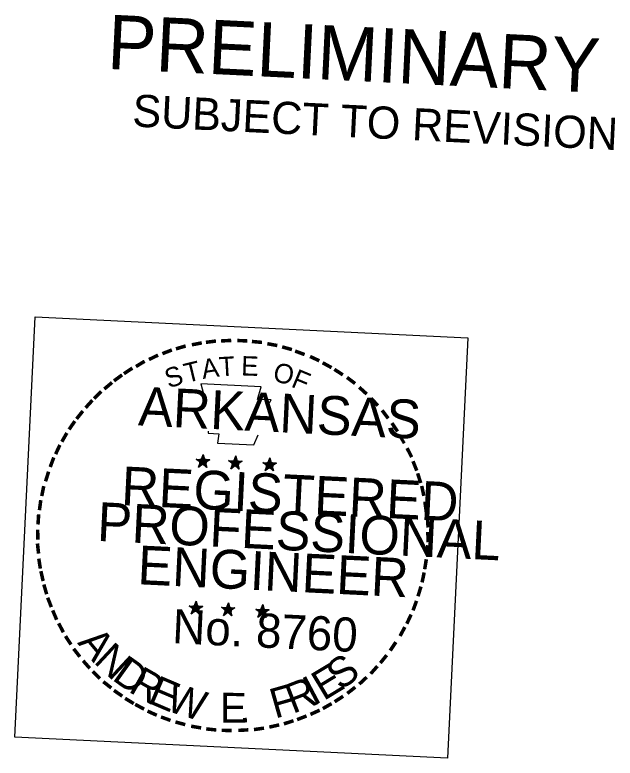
# Model space of a CAD drawing. Extents: x 669100 to 670801, y 741155 to 743955.
# Drawn here: x 669099.6 to 669177, y 743722.6 to 743818.4 of the extents above; entities that cross this region are included whole.
import ezdxf

# ---------------------------------------------------------------- set-up
doc = ezdxf.new("R2010")
doc.units = 0
doc.layers.add('R_Border PE', color=7, linetype='Continuous')
doc.layers.add('R_Border Prem', color=7, linetype='Continuous')

msp = doc.modelspace()

# ---------------------------------------------------------------- linework, layer by layer
at = {"layer": 'R_Border PE'}
for p, q in [((669123.901, 743761.791), (669123.745, 743761.172)), ((669123.901, 743761.791), (669123.769, 743761.146)), ((669123.901, 743761.791), (669123.845, 743761.168)), ((669123.856, 743760.867), (669123.901, 743761.791)), ((669123.901, 743761.791), (669124.044, 743761.133)), ((669123.901, 743761.791), (669123.995, 743761.16)), ((669123.901, 743761.791), (669123.945, 743761.163)), ((669122.995, 743761.184), (669123.856, 743760.867)), ((669122.995, 743761.184), (669123.642, 743761.102)), ((669122.995, 743761.184), (669123.639, 743761.052)), ((669122.995, 743761.184), (669123.612, 743761.004)), ((669122.995, 743761.184), (669123.607, 743760.904)), ((669122.995, 743761.184), (669123.58, 743760.855)), ((669122.995, 743761.184), (669123.577, 743760.805)), ((669123.295, 743760.143), (669123.856, 743760.867)), ((669124.743, 743761.099), (669123.856, 743760.867)), ((669124.369, 743760.091), (669123.856, 743760.867)), ((669124.743, 743761.099), (669123.966, 743761.087)), ((669124.743, 743761.099), (669124.01, 743760.959)), ((669124.743, 743761.099), (669124.013, 743761.009)), ((669124.369, 743760.091), (669124.054, 743760.832)), ((669124.369, 743760.091), (669124.105, 743760.855)), ((669124.743, 743761.099), (669124.183, 743760.901)), ((669124.743, 743761.099), (669124.231, 743760.873)), ((669124.743, 743761.099), (669124.255, 743760.847)), ((669127.165, 743760.981), (669128.026, 743760.664)), ((669127.165, 743760.981), (669127.812, 743760.9)), ((669127.165, 743760.981), (669127.81, 743760.85)), ((669127.165, 743760.981), (669127.782, 743760.801)), ((669127.165, 743760.981), (669127.752, 743760.702)), ((669127.165, 743760.981), (669127.75, 743760.653)), ((669127.165, 743760.981), (669127.747, 743760.603)), ((669128.071, 743761.588), (669127.915, 743760.97)), ((669128.071, 743761.588), (669127.939, 743760.944)), ((669128.071, 743761.588), (669127.99, 743760.966)), ((669128.026, 743760.664), (669128.071, 743761.588)), ((669128.913, 743760.896), (669128.026, 743760.664)), ((669128.071, 743761.588), (669128.214, 743760.93)), ((669128.071, 743761.588), (669128.165, 743760.958)), ((669128.071, 743761.588), (669128.09, 743760.961)), ((669128.913, 743760.896), (669128.137, 743760.884)), ((669128.913, 743760.896), (669128.18, 743760.757)), ((669128.913, 743760.896), (669128.183, 743760.807)), ((669128.913, 743760.896), (669128.353, 743760.698)), ((669128.913, 743760.896), (669128.402, 743760.671)), ((669128.913, 743760.896), (669128.425, 743760.645)), ((669132.488, 743761.324), (669132.309, 743760.731)), ((669132.488, 743761.324), (669132.358, 743760.704)), ((669132.488, 743761.324), (669132.408, 743760.702)), ((669132.444, 743760.425), (669132.488, 743761.324)), ((669132.488, 743761.324), (669132.633, 743760.691)), ((669132.488, 743761.324), (669132.583, 743760.693)), ((669132.488, 743761.324), (669132.509, 743760.722)), ((669123.295, 743760.143), (669123.604, 743760.829)), ((669123.295, 743760.143), (669123.625, 743760.753)), ((669123.295, 743760.143), (669123.674, 743760.725)), ((669123.295, 743760.143), (669123.846, 743760.667)), ((669123.295, 743760.143), (669123.745, 743760.647)), ((669123.295, 743760.143), (669123.867, 743760.591)), ((669124.369, 743760.091), (669123.842, 743760.592)), ((669124.369, 743760.091), (669123.846, 743760.667)), ((669124.369, 743760.091), (669123.945, 743760.637)), ((669124.369, 743760.091), (669124.024, 743760.733)), ((669127.465, 743759.941), (669128.026, 743760.664)), ((669127.465, 743759.941), (669127.774, 743760.626)), ((669127.465, 743759.941), (669127.795, 743760.55)), ((669127.465, 743759.941), (669127.844, 743760.523)), ((669127.465, 743759.941), (669128.016, 743760.464)), ((669127.465, 743759.941), (669127.915, 743760.444)), ((669127.465, 743759.941), (669128.037, 743760.388)), ((669128.539, 743759.888), (669128.012, 743760.389)), ((669128.539, 743759.888), (669128.016, 743760.464)), ((669128.539, 743759.888), (669128.026, 743760.664)), ((669128.539, 743759.888), (669128.115, 743760.435)), ((669128.539, 743759.888), (669128.195, 743760.531)), ((669128.539, 743759.888), (669128.224, 743760.629)), ((669128.539, 743759.888), (669128.275, 743760.652)), ((669131.584, 743760.742), (669132.444, 743760.425)), ((669131.584, 743760.742), (669132.229, 743760.635)), ((669131.584, 743760.742), (669132.202, 743760.587)), ((669131.584, 743760.742), (669132.201, 743760.562)), ((669131.584, 743760.742), (669132.171, 743760.463)), ((669131.584, 743760.742), (669132.168, 743760.413)), ((669131.584, 743760.742), (669132.166, 743760.363)), ((669131.859, 743759.702), (669132.444, 743760.425)), ((669131.859, 743759.702), (669132.192, 743760.387)), ((669131.859, 743759.702), (669132.214, 743760.311)), ((669131.859, 743759.702), (669132.262, 743760.283)), ((669131.859, 743759.702), (669132.435, 743760.225)), ((669131.859, 743759.702), (669132.334, 743760.205)), ((669131.859, 743759.702), (669132.456, 743760.149)), ((669132.932, 743759.65), (669132.431, 743760.15)), ((669132.932, 743759.65), (669132.435, 743760.225)), ((669133.332, 743760.657), (669132.444, 743760.425)), ((669132.932, 743759.65), (669132.444, 743760.425)), ((669132.932, 743759.65), (669132.533, 743760.195)), ((669133.332, 743760.657), (669132.555, 743760.644)), ((669133.332, 743760.657), (669132.599, 743760.517)), ((669133.332, 743760.657), (669132.601, 743760.567)), ((669132.932, 743759.65), (669132.613, 743760.291)), ((669132.932, 743759.65), (669132.643, 743760.39)), ((669132.932, 743759.65), (669132.693, 743760.387)), ((669133.332, 743760.657), (669132.771, 743760.459)), ((669133.332, 743760.657), (669132.795, 743760.433)), ((669133.332, 743760.657), (669132.844, 743760.405)), ((669122.981, 743742.863), (669122.803, 743742.271)), ((669122.981, 743742.863), (669122.851, 743742.243)), ((669122.981, 743742.863), (669122.901, 743742.241)), ((669122.938, 743741.964), (669122.981, 743742.863)), ((669122.981, 743742.863), (669123.126, 743742.23)), ((669122.981, 743742.863), (669123.076, 743742.233)), ((669122.981, 743742.863), (669123.001, 743742.236)), ((669127.152, 743742.66), (669126.973, 743742.068)), ((669127.152, 743742.66), (669127.021, 743742.041)), ((669127.152, 743742.66), (669127.071, 743742.039)), ((669127.108, 743741.761), (669127.152, 743742.66)), ((669127.152, 743742.66), (669127.271, 743742.029)), ((669127.152, 743742.66), (669127.246, 743742.03)), ((669127.152, 743742.66), (669127.171, 743742.034)), ((669122.077, 743742.281), (669122.938, 743741.964)), ((669122.077, 743742.281), (669122.723, 743742.175)), ((669122.077, 743742.281), (669122.695, 743742.126)), ((669122.077, 743742.281), (669122.694, 743742.101)), ((669122.077, 743742.281), (669122.664, 743742.002)), ((669122.077, 743742.281), (669122.662, 743741.952)), ((669122.077, 743742.281), (669122.659, 743741.902)), ((669122.352, 743741.241), (669122.938, 743741.964)), ((669122.352, 743741.241), (669122.686, 743741.926)), ((669122.352, 743741.241), (669122.706, 743741.825)), ((669122.352, 743741.241), (669122.755, 743741.798)), ((669122.352, 743741.241), (669122.928, 743741.764)), ((669122.352, 743741.241), (669122.827, 743741.744)), ((669122.352, 743741.241), (669122.924, 743741.689)), ((669123.426, 743741.189), (669122.899, 743741.69)), ((669123.426, 743741.189), (669122.927, 743741.739)), ((669123.825, 743742.196), (669122.938, 743741.964)), ((669123.426, 743741.189), (669122.938, 743741.964)), ((669123.426, 743741.189), (669123.002, 743741.736)), ((669123.825, 743742.196), (669123.049, 743742.184)), ((669123.825, 743742.196), (669123.092, 743742.057)), ((669123.825, 743742.196), (669123.095, 743742.106)), ((669123.426, 743741.189), (669123.107, 743741.831)), ((669123.426, 743741.189), (669123.111, 743741.93)), ((669123.426, 743741.189), (669123.186, 743741.927)), ((669123.825, 743742.196), (669123.24, 743741.999)), ((669123.825, 743742.196), (669123.289, 743741.972)), ((669123.825, 743742.196), (669123.336, 743741.92)), ((669126.247, 743742.079), (669127.108, 743741.761)), ((669126.247, 743742.079), (669126.868, 743741.973)), ((669126.247, 743742.079), (669126.865, 743741.923)), ((669126.247, 743742.079), (669126.864, 743741.898)), ((669126.247, 743742.079), (669126.834, 743741.8)), ((669126.247, 743742.079), (669126.832, 743741.75)), ((669126.247, 743742.079), (669126.83, 743741.7)), ((669126.522, 743741.039), (669127.108, 743741.761)), ((669126.522, 743741.039), (669126.856, 743741.724)), ((669127.97, 743741.995), (669127.108, 743741.761)), ((669127.596, 743740.987), (669127.108, 743741.761)), ((669127.97, 743741.995), (669127.219, 743741.981)), ((669127.97, 743741.995), (669127.263, 743741.854)), ((669127.97, 743741.995), (669127.265, 743741.904)), ((669127.596, 743740.987), (669127.281, 743741.728)), ((669127.596, 743740.987), (669127.356, 743741.724)), ((669127.97, 743741.995), (669127.41, 743741.797)), ((669127.97, 743741.995), (669127.459, 743741.769)), ((669127.97, 743741.995), (669127.506, 743741.717)), ((669130.666, 743741.839), (669131.526, 743741.522)), ((669130.666, 743741.839), (669131.286, 743741.734)), ((669130.666, 743741.839), (669131.284, 743741.684)), ((669130.666, 743741.839), (669131.257, 743741.635)), ((669130.666, 743741.839), (669131.253, 743741.56)), ((669130.666, 743741.839), (669131.224, 743741.486)), ((669130.666, 743741.839), (669131.222, 743741.437)), ((669131.57, 743742.421), (669131.39, 743741.804)), ((669131.57, 743742.421), (669131.44, 743741.801)), ((669131.57, 743742.421), (669131.49, 743741.799)), ((669131.526, 743741.522), (669131.57, 743742.421)), ((669132.389, 743741.755), (669131.526, 743741.522)), ((669131.57, 743742.421), (669131.69, 743741.789)), ((669131.57, 743742.421), (669131.665, 743741.79)), ((669131.57, 743742.421), (669131.59, 743741.794)), ((669132.389, 743741.755), (669131.637, 743741.742)), ((669132.389, 743741.755), (669131.681, 743741.614)), ((669132.389, 743741.755), (669131.684, 743741.664)), ((669132.389, 743741.755), (669131.829, 743741.557)), ((669132.389, 743741.755), (669131.876, 743741.505)), ((669132.389, 743741.755), (669131.9, 743741.479)), ((669126.522, 743741.039), (669126.876, 743741.623)), ((669126.522, 743741.039), (669126.925, 743741.595)), ((669126.522, 743741.039), (669127.098, 743741.562)), ((669126.522, 743741.039), (669126.997, 743741.542)), ((669126.522, 743741.039), (669127.095, 743741.487)), ((669127.596, 743740.987), (669127.07, 743741.488)), ((669127.596, 743740.987), (669127.097, 743741.537)), ((669127.596, 743740.987), (669127.172, 743741.533)), ((669127.596, 743740.987), (669127.277, 743741.628)), ((669130.941, 743740.799), (669131.526, 743741.522)), ((669130.941, 743740.799), (669131.249, 743741.485)), ((669130.941, 743740.799), (669131.269, 743741.384)), ((669130.941, 743740.799), (669131.343, 743741.356)), ((669130.941, 743740.799), (669131.416, 743741.302)), ((669130.941, 743740.799), (669131.491, 743741.298)), ((669130.941, 743740.799), (669131.513, 743741.247)), ((669132.014, 743740.747), (669131.487, 743741.223)), ((669132.014, 743740.747), (669131.491, 743741.298)), ((669132.014, 743740.747), (669131.526, 743741.522)), ((669132.014, 743740.747), (669131.59, 743741.293)), ((669132.014, 743740.747), (669131.669, 743741.365)), ((669132.014, 743740.747), (669131.7, 743741.488)), ((669132.014, 743740.747), (669131.75, 743741.486))]:
    msp.add_line(p, q, dxfattribs=at)
for points in [[(669123.59, 743770.866), (669124.139, 743768.762)], [(669132.244, 743768.143), (669132.627, 743768.826), (669130.902, 743768.859), (669131.356, 743770.489), (669123.59, 743770.866)], [(669124.521, 743764.764), (669124.51, 743764.539), (669125.906, 743764.421), (669125.724, 743763.254), (669130.393, 743763.027), (669130.957, 743764.326)], [(669123.901, 743761.791), (669124.369, 743760.091), (669122.995, 743761.184), (669124.743, 743761.099), (669123.295, 743760.143), (669123.901, 743761.791)], [(669128.071, 743761.588), (669128.539, 743759.888), (669127.165, 743760.981), (669128.913, 743760.896), (669127.465, 743759.941), (669128.071, 743761.588)], [(669132.488, 743761.324), (669132.932, 743759.65), (669131.584, 743760.742), (669133.332, 743760.657), (669131.859, 743759.702), (669132.488, 743761.324)], [(669122.981, 743742.863), (669123.426, 743741.189), (669122.077, 743742.281), (669123.825, 743742.196), (669122.352, 743741.241), (669122.981, 743742.863)], [(669127.152, 743742.66), (669127.596, 743740.987), (669126.247, 743742.079), (669127.97, 743741.995), (669126.522, 743741.039), (669127.152, 743742.66)], [(669131.57, 743742.421), (669132.014, 743740.747), (669130.666, 743741.839), (669132.389, 743741.755), (669130.941, 743740.799), (669131.57, 743742.421)]]:
    msp.add_lwpolyline(points, dxfattribs=at)
for centre, radius in [((669123.863, 743760.864), 0.431), ((669123.863, 743760.864), 0.39), ((669123.863, 743760.864), 0.361), ((669123.863, 743760.864), 0.332), ((669123.863, 743760.864), 0.289), ((669123.863, 743760.864), 0.269), ((669123.863, 743760.864), 0.248), ((669123.863, 743760.864), 0.213), ((669123.863, 743760.864), 0.187), ((669123.863, 743760.864), 0.155), ((669123.863, 743760.864), 0.124), ((669123.863, 743760.864), 0.0924), ((669123.863, 743760.864), 0.0741), ((669123.863, 743760.864), 0.036), ((669128.031, 743760.662), 0.431), ((669128.031, 743760.662), 0.39), ((669128.031, 743760.662), 0.361), ((669128.031, 743760.662), 0.332), ((669128.031, 743760.662), 0.289), ((669128.031, 743760.662), 0.269), ((669128.031, 743760.662), 0.248), ((669128.031, 743760.662), 0.213), ((669128.031, 743760.662), 0.187), ((669132.442, 743760.418), 0.431), ((669128.031, 743760.662), 0.155), ((669128.031, 743760.662), 0.124), ((669128.031, 743760.662), 0.0924), ((669128.031, 743760.662), 0.0741), ((669128.031, 743760.662), 0.036), ((669132.442, 743760.418), 0.39), ((669132.442, 743760.418), 0.361), ((669132.442, 743760.418), 0.332), ((669132.442, 743760.418), 0.289), ((669132.442, 743760.418), 0.269), ((669132.442, 743760.418), 0.248), ((669132.442, 743760.418), 0.213), ((669132.442, 743760.418), 0.187), ((669132.442, 743760.418), 0.155), ((669132.442, 743760.418), 0.124), ((669132.442, 743760.418), 0.0924), ((669132.442, 743760.418), 0.0741), ((669132.442, 743760.418), 0.036), ((669122.934, 743741.954), 0.431), ((669122.934, 743741.954), 0.39), ((669122.934, 743741.954), 0.361), ((669122.934, 743741.954), 0.332), ((669122.934, 743741.954), 0.289), ((669122.934, 743741.954), 0.269), ((669122.934, 743741.954), 0.248), ((669122.934, 743741.954), 0.213), ((669122.934, 743741.954), 0.187), ((669122.934, 743741.954), 0.155), ((669122.934, 743741.954), 0.124), ((669122.934, 743741.954), 0.0924), ((669122.934, 743741.954), 0.0741), ((669122.934, 743741.954), 0.036), ((669127.102, 743741.752), 0.431), ((669127.102, 743741.752), 0.39), ((669127.102, 743741.752), 0.361), ((669127.102, 743741.752), 0.332), ((669127.102, 743741.752), 0.289), ((669127.102, 743741.752), 0.269), ((669127.102, 743741.752), 0.248), ((669127.102, 743741.752), 0.213), ((669127.102, 743741.752), 0.187), ((669127.102, 743741.752), 0.155), ((669127.102, 743741.752), 0.124), ((669127.102, 743741.752), 0.0924), ((669127.102, 743741.752), 0.0741), ((669127.102, 743741.752), 0.036), ((669131.514, 743741.509), 0.431), ((669131.514, 743741.509), 0.39), ((669131.514, 743741.509), 0.361), ((669131.514, 743741.509), 0.332), ((669131.514, 743741.509), 0.289), ((669131.514, 743741.509), 0.269), ((669131.514, 743741.509), 0.248), ((669131.514, 743741.509), 0.213), ((669131.514, 743741.509), 0.187), ((669131.514, 743741.509), 0.155), ((669131.514, 743741.509), 0.124), ((669131.514, 743741.509), 0.0924), ((669131.514, 743741.509), 0.0741), ((669131.514, 743741.509), 0.036)]:
    msp.add_circle(centre, radius, dxfattribs=at)
at = {"layer": 'R_Border Prem'}
msp.add_lwpolyline([(669102.248, 743779.53), (669157.982, 743776.823), (669155.35, 743722.639), (669099.616, 743725.345)], close=True, dxfattribs=at)

# ---------------------------------------------------------------- texts
at = {"layer": 'R_Border PE'}
for s, height, rotation, p in [('-', 3.999, 10.85007, (669122.483, 743774.349)), ('-', 4, 7.43927, (669124.2, 743774.666)), ('-', 3.999, 3.11674, (669126.037, 743774.852)), ('-', 3.999, 357.40615, (669127.968, 743774.934)), ('-', 4, 354.96296, (669129.789, 743774.82)), ('-', 4, 349.38165, (669131.63, 743774.581)), ('-', 4, 21.52713, (669118.975, 743773.243)), ('-', 3.999, 16.39601, (669120.581, 743773.841)), ('-', 4, 344.42481, (669133.415, 743774.219)), ('-', 4, 339.55612, (669134.968, 743773.743)), ('-', 4, 26.01174, (669117.363, 743772.52)), ('T', 2.5, 3.24268, (669125.99, 743771.826)), ('E', 2.5, 358.05226, (669128.75, 743771.967)), ('-', 4, 335.07501, (669136.789, 743773.104)), ('-', 4, 31.28349, (669115.82, 743771.669)), ('T', 2.499, 13.62352, (669121.744, 743770.981)), ('A', 2.5, 8.4331, (669123.847, 743771.505)), ('O', 2.499, 347.67142, (669132.745, 743771.248)), ('-', 4, 331.34101, (669138.33, 743772.353)), ('-', 3.999, 33.45166, (669114.325, 743770.766)), ('S', 2.499, 18.81394, (669119.431, 743770.267)), ('F', 2.499, 337.29058, (669135.089, 743770.558)), ('-', 3.999, 326.86082, (669139.744, 743771.584)), ('-', 3.999, 36.17058, (669113.105, 743769.874)), ('-', 3.999, 323.08258, (669141.299, 743770.607)), ('-', 3.999, 40.18217, (669111.955, 743768.878)), ('ARKANSAS', 5, 357.21992, (669115.447, 743765.53)), ('-', 4, 317.74963, (669142.77, 743769.459)), ('-', 4, 45.64297, (669110.773, 743767.734)), ('-', 3.999, 47.8341, (669109.716, 743766.584)), ('-', 4, 312.79851, (669144.209, 743768.163)), ('-', 3.999, 307.09965, (669145.565, 743766.721)), ('-', 4, 51.45239, (669108.623, 743765.211)), ('-', 4, 55.29055, (669107.735, 743763.927)), ('-', 3.999, 303.8721, (669146.791, 743765.159)), ('-', 3.999, 60.09127, (669106.887, 743762.442)), ('-', 3.5, 300.89521, (669147.945, 743763.677)), ('-', 3.999, 64.99419, (669106.164, 743760.95)), ('-', 4, 296.88827, (669148.67, 743762.115)), ('-', 3.999, 69.61439, (669105.538, 743759.403)), ('-', 3.999, 291.88272, (669149.396, 743760.553)), ('REGISTERED', 5, 357.21992, (669113.246, 743755.25)), ('-', 4, 72.68088, (669104.976, 743757.629)), ('-', 3.999, 287.79275, (669149.976, 743759.098)), ('-', 3.999, 78.42119, (669104.541, 743755.873)), ('-', 4, 282.34318, (669150.48, 743757.622)), ('-', 3.999, 82.40626, (669104.282, 743754.158)), ('PROFESSIONAL', 4.99995, 357.21992, (669110.144, 743750.645)), ('-', 4, 277.76926, (669150.888, 743755.724)), ('-', 4, 86.28216, (669104.122, 743752.414)), ('-', 4, 273.81608, (669151.22, 743753.806)), ('-', 3.999, 91.4158, (669104.134, 743750.586)), ('-', 4, 271.55003, (669151.282, 743751.976)), ('-', 3.999, 96.16785, (669104.229, 743748.93)), ('ENGINEER', 5, 357.21992, (669115.354, 743745.06)), ('-', 3.999, 267.16059, (669151.28, 743750.399)), ('-', 4, 98.93487, (669104.464, 743747.066)), ('-', 3.999, 260.73712, (669151.15, 743748.754)), ('-', 4, 102.67777, (669104.816, 743745.572)), ('-', 4, 258.21521, (669150.895, 743747.114)), ('-', 3.999, 106.30734, (669105.264, 743743.973)), ('-', 3.999, 252.98253, (669150.538, 743745.429)), ('-', 3.999, 111.28424, (669105.841, 743742.444)), ('-', 4, 250.08801, (669150.002, 743743.653)), ('-', 3.999, 112.94877, (669106.515, 743740.859)), ('No. 8760', 4.4, 357.21992, (669119.835, 743737.459)), ('-', 4, 245.10859, (669149.371, 743742.007)), ('-', 4, 117.66704, (669107.343, 743739.367)), ('A', 3.849, 309.69259, (669107.602, 743737.475)), ('-', 4, 241.83964, (669148.62, 743740.467)), ('-', 4, 123.11337, (669108.274, 743737.92)), ('N', 3.849, 317.05608, (669109.657, 743735)), ('-', 4, 236.29117, (669147.556, 743738.641)), ('-', 3.999, 127.93804, (669109.355, 743736.466)), ('-', 4, 231.06516, (669146.478, 743737.066)), ('-', 4, 131.44373, (669110.588, 743735.055)), ('D', 3.849, 324.41957, (669112.013, 743732.808)), ('S', 3.849, 36.94295, (669141.607, 743731.259)), ('R', 3.849, 330.39371, (669114.118, 743731.263)), ('E', 3.849, 31.10774, (669139.406, 743729.971)), ('-', 4, 228.47369, (669145.335, 743735.695)), ('-', 4, 136.15374, (669111.831, 743733.843)), ('E', 3.849, 336.9236, (669116.588, 743729.836)), ('I', 3.849, 27.77333, (669138.093, 743729.337)), ('-', 3.999, 222.98525, (669144.069, 743734.355)), ('-', 3.999, 141.86626, (669113.179, 743732.751)), ('W', 3.849, 342.75881, (669118.921, 743728.805)), ('F', 3.849, 15.82503, (669133.137, 743727.715)), ('R', 3.849, 21.24345, (669135.426, 743728.322)), ('-', 4, 145.30971, (669114.533, 743731.76)), ('-', 3.999, 218.30501, (669142.708, 743733.145)), ('-', 3.999, 148.79031, (669115.941, 743730.865)), ('E', 3.849, 359.50032, (669126.041, 743727.221)), ('-', 3.999, 212.95626, (669141.278, 743732.038)), ('-', 3.999, 151.82012, (669117.211, 743730.203)), ('-', 4, 209.46901, (669139.882, 743731.129)), ('-', 4, 155.78114, (669118.752, 743729.477)), ('-', 3.999, 201.47154, (669136.854, 743729.599)), ('-', 4, 204.57676, (669138.466, 743730.322)), ('-', 4, 160.01819, (669120.425, 743728.87)), ('-', 4, 164.77544, (669122.203, 743728.384)), ('.', 3.849, 5.33554, (669128.591, 743727.165)), ('-', 4, 197.93834, (669135.274, 743729)), ('-', 4, 170.33538, (669124.113, 743728.016)), ('-', 4, 173.73819, (669125.978, 743727.775)), ('-', 4, 178.81168, (669127.828, 743727.735)), ('-', 3.999, 183.03659, (669129.861, 743727.837)), ('-', 4, 188.50568, (669131.724, 743728.071)), ('-', 3.999, 192.69421, (669133.571, 743728.482))]:
    msp.add_text(s, height=height, rotation=rotation, dxfattribs=at).set_placement(p)
at = {"layer": 'R_Border Prem'}
for s, height, p in [('PRELIMINARY', 7.00001, (669111.433, 743811.48)), ('SUBJECT TO REVISION', 4.15022, (669114.693, 743804.054))]:
    msp.add_text(s, height=height, rotation=357.20084, dxfattribs=at).set_placement(p)

doc.saveas('drawing.dxf')
